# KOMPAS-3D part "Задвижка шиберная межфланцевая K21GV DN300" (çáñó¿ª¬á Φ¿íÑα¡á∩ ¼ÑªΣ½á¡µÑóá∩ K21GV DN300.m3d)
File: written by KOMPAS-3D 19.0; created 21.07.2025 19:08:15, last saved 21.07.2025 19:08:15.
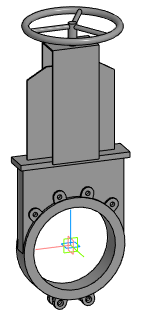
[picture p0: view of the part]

Document properties: Автор: Евгений; Полное имя файла: E:\Dendor Работа Сачек\3D для проектировщиков\2.3 Тип K21GV. Задвижка шиберная межфланцевая\stp_Задвижка шиберная K21GV DN50-400 с маховиком\Задвижка шиберная межфланцевая K21GV DN300.m3d

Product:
- Part/product: Задвижка шиберная межфланцевая K21GV DN300

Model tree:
1. Операция без истории:1  (labels: Задвижка шиберная межфланцевая K21GV DN300)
